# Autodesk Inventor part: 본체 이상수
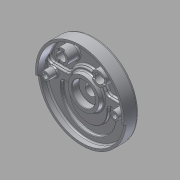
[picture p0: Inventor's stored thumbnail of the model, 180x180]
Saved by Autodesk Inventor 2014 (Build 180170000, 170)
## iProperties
Created: 2015-05
Part Number: 본체 이상수
Material: 알루미늄 6061
Document SubType Name: Modeling
Designer: USER
Density: 2.71 g/cm^3
Appearance: 알루미늄 - 평지
Mass: 1091.66 g
Surface Area: 1039.9 cm^2
Volume: 402.825 cm^3
Author: USER
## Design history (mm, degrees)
sketch "스케치1"
  geometry: C1 r 95 at (0, 0); 1 further point
  constraints: 1 centre point, 1 coincident
  dimensions: "d0" = 190 diameter of C1
extrude "돌출1" new body sketch "스케치1" distance "d1" = 32; taper "d2" = 0 deg
sketch "스케치2"
  geometry: L1 (0, 0)-(-94.638, -8.28); L2 (0, 0)-(94.638, -8.28); L3 (-90, 0)-(90, 0); A1 r 95 centre (0, 0) between (94.638, -8.28) and (-94.638, -8.28) reference
  constraints: 6 end point, 2 point on circle, 1 coincident, 1 horizontal, 1 midpoint
  dimensions: "d4" = 5 deg angle of L2 L3; "d5" = 5 deg angle of L1 L3
extrude "돌출2" cut sketch "스케치2" distance "d6" = 5; taper "d7" = 0 deg
sketch "스케치3"
  geometry: C1 r 95 at (0, 0) reference; C2 r 25 at (0, 0)
  constraints: 1 centre point, 1 coincident
  dimensions: "d8" = 50 diameter of C2
extrude "돌출3" join sketch "스케치3" distance "d9" = 12; taper "d10" = -15 deg
sketch "스케치4"
  geometry: L1 (-89.196, 12)-(-40.249, 12); L2 (40.249, 12)-(89.196, 12); A1 r 95 centre (0, 0) between (94.638, -8.28) and (-94.638, -8.28) reference; A2 r 42 centre (0, 0) between (40.249, 12) and (-40.249, 12); A3 r 90 centre (0, 0) between (89.196, 12) and (-89.196, 12); 1 further point
  constraints: 4 end point, 4 point on circle, 2 centre point, 2 coincident, 2 horizontal
  dimensions: "d11" = 84 diameter of A2; "d12" = 180 diameter of A3; "d14" = 12 distance from line of point (0, 0) L2; "d15" = 12 distance from line of point (0, 0) L1
extrude "돌출4" cut sketch "스케치4" distance "d16" = 25; taper "d17" = 0 deg
fillet "모깎기1" dims "d18" = 10
sketch "스케치5"
  geometry: L1 (-47.117, 12)-(-76.916, 12) reference; L2 (76.916, 12)-(47.117, 12) reference; C1 r 42 at (0, 0); C2 r 90 at (0, 0); A1 r 42 centre (0, 0) between (38.056, 17.769) and (-38.056, 17.769) reference; A2 r 10 centre (-47.117, 22) between (-47.117, 12) and (-38.056, 17.769) reference; A3 r 10 centre (-76.916, 22) between (-86.53, 24.75) and (-76.916, 12) reference; A4 r 90 centre (0, 0) between (86.53, 24.75) and (-86.53, 24.75) reference; A5 r 10 centre (76.916, 22) between (76.916, 12) and (86.53, 24.75) reference; A6 r 10 centre (47.117, 22) between (38.056, 17.769) and (47.117, 12) reference; A7 r 95 centre (0, 0) between (94.638, -8.28) and (-94.638, -8.28) reference
  constraints: 2 centre point, 2 coincident
  dimensions: "d19" = 84 diameter of C1; "d20" = 180 diameter of C2
extrude "돌출5" cut sketch "스케치5" distance "d21" = 18; taper "d22" = 0 deg
sketch "스케치7"
  geometry: C1 r 15 at (-40, 52); C2 r 15 at (40, 52); A1 r 90 centre (0, 0) between (86.53, 24.75) and (-86.53, 24.75) reference
  constraints: 2 centre point, 1 equal radius, 1 horizontal alignment
  dimensions: "d23" = 30 diameter of C1; "d24" = 40 horizontal distance of C1.centre A1.centre; "d25" = 80 distance of C2.centre C1.centre; "d26" = 52 vertical distance of A1.centre C1.centre
extrude "돌출6" join sketch "스케치7" distance "d27" = 25; taper "d28" = 0 deg
sketch "스케치8"
  geometry: C1 r 15 at (-40, -52) reference; C2 r 15 at (40, -52) reference; C3 r 10 at (40, -52); C4 r 10 at (-40, -52)
  constraints: 2 centre point, 2 coincident
  dimensions: "d29" = 20 diameter of C3; "d30" = 20 diameter of C4
extrude "돌출7" cut sketch "스케치8" stored distance "d31" = 0; taper "d32" = 0 deg
sketch "스케치9"
  geometry: L1 (-6, 13.748)-(-6, -13.748); L2 (6, 13.748)-(6, -13.748); L3 (66.252, 6)-(93.748, 6); L4 (66.252, -6)-(93.748, -6); C1 r 10 at (0, 0) reference; C2 r 10 at (80, 0) reference; A1 r 15 centre (0, 0) between (-6, 13.748) and (6, 13.748) reference; A2 r 15 centre (80, 0) between (93.748, 6) and (93.748, -6) reference; 1 further point
  constraints: 8 end point, 8 point on circle, 2 parallel, 1 perpendicular, 1 vertical
  dimensions: "d33" = 6 distance from line of C1.centre L1; "d34" = 12 distance between parallel lines of L2 L1; "d35" = 6 distance from line of L3 C2.centre; "d36" = 12 distance between parallel lines of L4 L3
extrude "돌출8" cut sketch "스케치9" distance "d37" = 3; taper "d38" = 0 deg
sketch "스케치10"
  geometry: C1 r 25 at (0, 0) reference; C2 r 9 at (74, 0); C3 r 9 at (-74, 0)
  constraints: 2 centre point, 2 horizontal alignment, 1 equal radius
  dimensions: "d39" = 18 diameter of C2; "d40" = 148 distance of C3.centre C2.centre; "d41" = 74 distance of C3.centre C1.centre
extrude "돌출9" join sketch "스케치10" distance "d42" = 32; taper "d43" = 0 deg
sketch "스케치11"
  geometry: C1 r 9 at (74, 0) reference; C2 r 9 at (-74, 0) reference; 2 further points
  constraints: 2 coincident
hole "구멍1" sketch "스케치11" at (74, 0), (-74, 0) diameter "d44" = 11; stored, may be unused: countersink angle "d48" = 90 deg, drill point angle "d50" = 118 deg; dims "d45" = 6, "d46" = 18, "d47" = 11, "d49" = 8
sketch "스케치12"
  geometry: C1 r 42 at (0, 0); A1 r 90 centre (0, 0) between (-86.53, 24.75) and (86.53, 24.75) reference
  constraints: 1 centre point, 1 coincident
  dimensions: "d51" = 84 diameter of C1
extrude "돌출10" cut sketch "스케치12" stored distance "d52" = 0; taper "d53" = 0 deg
sketch "스케치13"
  geometry: C1 r 35 at (0, 0); A1 r 90 centre (0, 0) between (-86.53, 24.75) and (86.53, 24.75) reference
  constraints: 1 centre point, 1 coincident
  dimensions: "d54" = 70 diameter of C1
extrude "돌출11" join sketch "스케치13" distance "d55" = 10; taper "d56" = -10 deg
sketch "스케치14"
  geometry: C1 r 33.237 at (0, 0) reference; 1 further point
  constraints: 1 coincident
hole "구멍2" sketch "스케치14" at (0, 0) diameter "d57" = 23; stored, may be unused: countersink angle "d61" = 90 deg, drill point angle "d63" = 118 deg; dims "d58" = 6, "d59" = 50, "d60" = 15, "d62" = 8
sketch "스케치15"
  geometry: L1 (-76.916, 12)-(-47.117, 12) reference; L2 (-50, -19)-(-50, -14); L3 (50, -19)-(50, -14); L4 (-59, -19)-(-59, -14); L5 (-41, -19)-(-41, -14); L6 (41, -19)-(41, -14); L7 (59, -19)-(59, -14); A1 r 35 centre (0, 0) between (-25.426, 24.053) and (25.426, 24.053) reference; A2 r 41 centre (0, -19) between (-41, -19) and (41, -19); A3 r 59 centre (0, -19) between (-59, -19) and (59, -19); A4 r 50 centre (0, -19) between (-50, -19) and (50, -19); A5 r 50 centre (0, -19) between (25.426, 24.053) and (-25.426, 24.053); A6 r 9 centre (50, -14) between (59, -14) and (41, -14); A7 r 9 centre (-50, -14) between (-41, -14) and (-59, -14); 3 further points
  constraints: 14 point on circle, 12 end point, 6 centre point, 6 tangent, 5 coincident, 3 parallel, 1 horizontal, 1 vertical, 1 vertical alignment, 10 other
  dimensions: "d65" = 19 dimension on A1.centre; "d68" = 41 radius of A2; "d69" = 59 radius of A3; "d72" = 50 radius of A4; "d73" = 5 distance of L2.start L2.end; "d74" = 5 distance of L3.start L3.end; "d75" = 18 diameter of A6; "d76" = 18 diameter of A7
extrude "돌출12" cut sketch "스케치15" distance "d77" = 7; taper "d78" = 0 deg
fillet "모깎기2" dims "d79" = 3
fillet "모깎기3" dims "d80" = 3
fillet "모깎기4" dims "d81" = 1
fillet "모깎기5" dims "d82" = 0.3
fillet "모깎기6" dims "d83" = 3
fillet "모깎기7" dims "d84" = 5
fillet "모깎기8" dims "d85" = 3
fillet "모깎기11" dims "d98" = 3
chamfer "모따기1" distance "d99" = 1; stored, may be unused: second distance "d100" = 2, angle "d101" = 45 deg
chamfer "모따기2" distance "d102" = 1; stored, may be unused: second distance "d103" = 2, angle "d104" = 45 deg
sketch "스케치19"
  geometry: L1 (0, 0)-(36.062, 36.062); L2 (36.062, 36.062)-(50.912, 50.912); L3 (0, 0)-(-36.062, 36.062); L4 (-36.062, 36.062)-(-50.912, 50.912); L5 (0, 0)-(0, 82.919); C1 r 90 at (0, 0) reference; A1 r 51 centre (0, 0) between (36.062, 36.062) and (-36.062, 36.062); A2 r 72 centre (0, 0) between (50.912, 50.912) and (-50.912, 50.912); 1 further point
  constraints: 10 end point, 4 point on circle, 2 centre point, 2 coincident, 1 midpoint, 1 point on line, 1 vertical, 1 other
  dimensions: "d119" = 90 deg angle of L3 L1; "d120" = 51 radius of A1; "d121" = 72 radius of A2
extrude "돌출14" join sketch "스케치19" distance "d110" = 5; taper "d111" = 0 deg
fillet "모깎기15" dims "d122" = 3
fillet "모깎기19" dims "d130" = 5
fillet "모깎기20" dims "d131" = 3
sketch "스케치22"
  geometry: C1 r 68 at (0, 0); A1 r 56 centre (0, 0) between (35.904, 42.975) and (-35.904, 42.975) reference
  constraints: 1 centre point, 1 coincident, 1 other
  dimensions: "d132" = 136 diameter of C1
feature "엠보싱4" sketch "스케치22" dims "d133" = 0.5, "d134" = 0
node "솔리드1"
node "투영된 루프1"
other parameters: "d13" = 12, "d66" = 82, "d67" = 118, "d86" = 144
